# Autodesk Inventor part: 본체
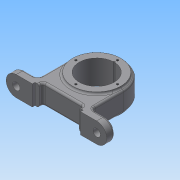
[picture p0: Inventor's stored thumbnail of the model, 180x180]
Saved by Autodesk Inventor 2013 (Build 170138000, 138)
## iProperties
Created: 2019-05
Part Number: 본체
Material: 일반
Document SubType Name: Modeling
Designer: Gpr
Density: 1 g/cm^3
Author: Gpr
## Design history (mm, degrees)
sketch "스케치1"
  geometry: L1 (-30, 0)-(-30, -6); L2 (-30, -6)-(-36, -6); L3 (-36, -6)-(-36, -10); L4 (-36, -10)-(-75, -10); L5 (-75, -10)-(-75, 2); L6 (-30, 0)-(0, 0); L7 (0, 10.162)-(0, 0); L8 (30, -6)-(36, -6); L9 (30, 0)-(30, -6); L10 (30, 0)-(0, 0); L11 (75, -10)-(75, 2); L12 (36, -10)-(75, -10); L13 (36, -6)-(36, -10); L14 (-40, 50)-(-40, 2); L15 (40, 50)-(40, 2); L16 (-75, 2)-(-40, 2); L17 (40, 2)-(75, 2); L18 (-40, 50)-(40, 50); A1 r 40 centre (0, 50) between (-40, 50) and (40, 50); 2 further points
  constraints: 36 end point, 8 symmetric about line, 5 horizontal, 5 vertical, 3 coincident, 2 point on circle, 1 centre point, 1 point on line, 1 tangent, 1 vertical alignment
  dimensions: "d4" = 10 distance between parallel lines of L6 L4; "d6" = 30 distance from line of point (0, 0) L1; "d7" = 4 distance between parallel lines of L4 L2; "d8" = 75 distance from line of point (0, 0) L5; "d9" = 72 distance between parallel lines of L13 L3; "d11" = 80 diameter of A1; "d12" = 60 distance from line of L4 A1.centre; "d13" = 12 distance between parallel lines of L4 L16
extrude "돌출1" new body sketch "스케치1" stored distance "d14" = 30; taper "d15" = 0 deg
sketch "스케치2"
  geometry: L1 (-30, 0)-(-30, -6) reference; L2 (-30, -6)-(-36, -6) reference; L3 (-36, -6)-(-36, -10) reference; L4 (-36, -10)-(-75, -10) reference; L5 (-75, -10)-(-75, 2) reference; L6 (-75, 2)-(-40, 2) reference; L7 (-40, 2)-(-40, 50) reference; L8 (40, 50)-(40, 2) reference; L9 (40, 2)-(75, 2) reference; L10 (75, 2)-(75, -10) reference; L11 (75, -10)-(36, -10) reference; L12 (36, -10)-(36, -6) reference; L13 (36, -6)-(30, -6) reference; L14 (30, -6)-(30, 0) reference; L15 (30, 0)-(-30, 0) reference; C1 r 36 at (0, 50); A1 r 40 centre (0, 50) between (40, 50) and (-40, 50) reference; 1 further point
  constraints: 1 centre point, 1 coincident
  dimensions: "d16" = 72 diameter of C1
extrude "돌출2" join sketch "스케치2" stored distance "d17" = 36; taper "d18" = 0 deg
sketch "스케치3"
  geometry: C1 r 36 at (0, 0) reference; C2 r 26 at (0, 0); 1 further point
  constraints: 1 centre point, 1 coincident
  dimensions: "d19" = 52 diameter of C2
extrude "돌출3" cut sketch "스케치3" stored distance "d21" = 36; taper "d22" = 0 deg
sketch "스케치4" dims "d23" = 62
  geometry: C1 r 26 at (0, 0) reference; C2 r 36 at (0, 0) reference; 3 further points
  constraints: 2 vertical alignment, 1 coincident, 2 other
hole "구멍1" sketch "스케치4" at (0, 31) diameter "d24" = 3.242; stored, may be unused: countersink angle "d28" = 90 deg, drill point angle "d30" = 118 deg; dims "d25" = 6, "d26" = 4, "d27" = 2, "d29" = 8
sketch "스케치5"
  geometry: L1 (0, 0)-(39, 0) reference; L2 (111, 0)-(150, 0) reference; C1 r 9 at (15, 15); C2 r 9 at (135, 15); 1 further point
  constraints: 2 centre point
  dimensions: "d34" = 18 diameter of C1; "d36" = 60 distance of point (75, 15) C1.centre; "d37" = 18 diameter of C2; "d38" = 60 distance of C2.centre point (75, 15); "d39" = 15 distance from line of L1 C1.centre; "d40" = 15 distance from line of C2.centre L2
extrude "돌출4" join sketch "스케치5" distance "d41" = 3; taper "d42" = 0 deg
sketch "스케치6"
  geometry: L1 (20, 15)-(100, 15) reference; L2 (100, 15)-(100, -15) reference; L3 (100, -15)-(20, -15) reference; L4 (20, -15)-(20, 15) reference; C1 r 9 at (0, 0) reference; C2 r 9 at (120, 0) reference; C3 r 5.5 at (0, 0); C4 r 5.5 at (120, 0); 1 further point
  constraints: 2 centre point, 2 coincident
  dimensions: "d43" = 11 diameter of C3; "d44" = 11 diameter of C4
extrude "돌출5" cut sketch "스케치6" stored distance "d45" = 3; taper "d46" = 0 deg
node "작업 평면1"
sketch "스케치7"
  geometry: 2 further points
  constraints: 2 coincident
hole "구멍2" sketch "스케치7" at (0, 0) diameter "d47" = 4.917; stored, may be unused: countersink angle "d51" = 90 deg, drill point angle "d53" = 118 deg; dims "d48" = 8, "d49" = 7, "d50" = 1, "d52" = 10
sketch "스케치8"
  geometry: C1 r 1.621 at (-31, 0) reference; C2 r 1.621 at (0, -31) reference; C3 r 1.621 at (31, 0) reference; C4 r 1.621 at (0, 31) reference; C5 r 36 at (0, 0) reference; C6 r 1.5 at (0, 26); 2 further points
  constraints: 2 vertical alignment, 1 centre point, 1 other
  dimensions: "d54" = 3 diameter of C6
extrude "돌출6" cut sketch "스케치8" stored distance "d56" = 3; taper "d57" = 0 deg
fillet "모깎기1" dims "d58" = 3
fillet "모깎기2" dims "d59" = 3
fillet "모깎기3" dims "d60" = 3
fillet "모깎기4" dims "d61" = 15
fillet "모깎기5" dims "d62" = 6
fillet "모깎기6" dims "d63" = 3
fillet "모깎기7" dims "d64" = 3
fillet "모깎기8" dims "d65" = 3
fillet "모깎기9" dims "d66" = 3
node "작업 평면2"
sketch "스케치9"
  geometry: 2 further points
  constraints: 1 vertical alignment, 1 other
  dimensions: "d68" = 7 distance of point (0, 7) point (0, 0)
feature "엠보싱1" sketch "스케치9" dims "d4" = 10, "d6" = 30, "d7" = 4, "d8" = 75, "d9" = 72, "d11" = 80, "d12" = 60, "d13" = 12, "d69" = 1, "d70" = 0
node "솔리드1"
pattern_circular "원형 패턴1" dims angle "d32" = 360 deg
mirror "대칭1"
node "절단 모서리 투영1"
node "절단 모서리 투영2"
node "절단 모서리 투영3"
node "절단 모서리 투영4"
node "절단 모서리 투영5"
other parameters: "d10" = 12, "d67" = 98
